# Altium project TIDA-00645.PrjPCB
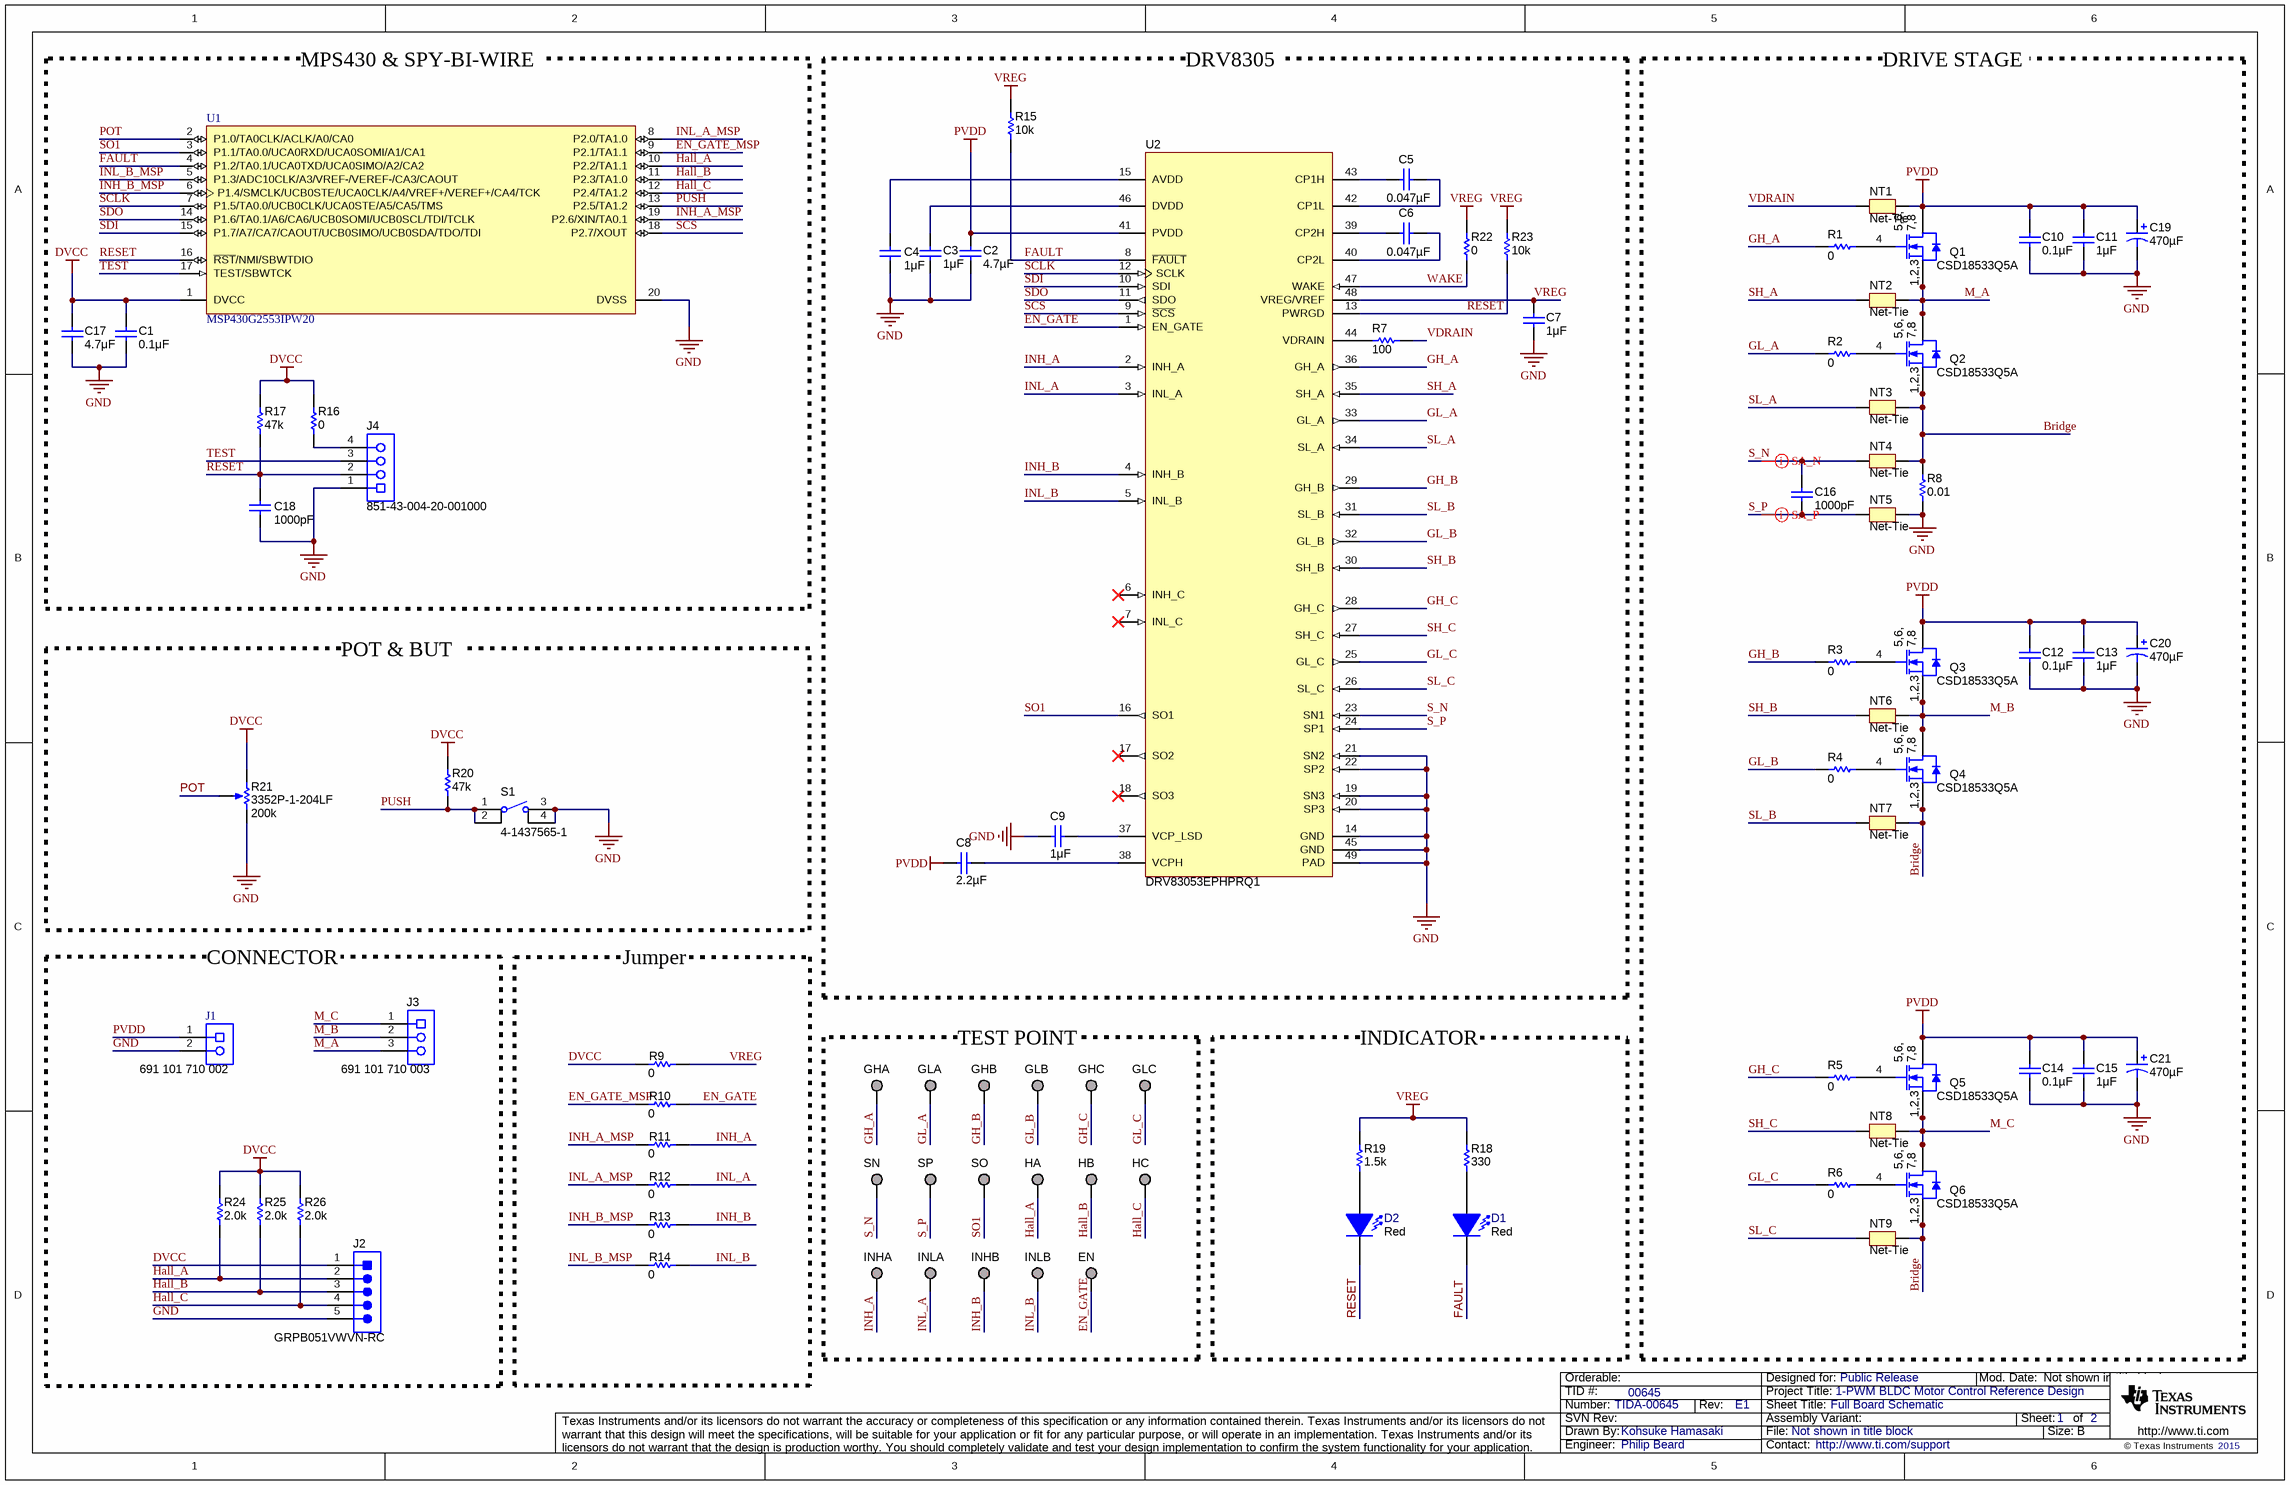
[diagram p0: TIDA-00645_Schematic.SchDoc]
TID: 00645; TechSupport: http://www.ti.com/support; SCH_Rev: E1; PRJ_Title: 1-PWM BLDC Motor Control Reference Design; PRJ_Number: TIDA-00645; PRJ_Engineer: Philip Beard; PRJ_Customer: Public Release; PCB_Rev: E1; PCB_Layout: Kohsuke Hamasaki; CopyrightYear: 2015
2 sheets, 98 parts. Net scope: global (net labels, ports and power ports of the same name join across sheets).
Board file: TIDA-00645_PCB layout.PcbDoc
Sheets:
  TIDA-00645_Schematic.SchDoc
  TIDA-00645_Hardware.SchDoc

## Sheet TIDA-00645_Schematic.SchDoc: Full Board Schematic
size 431 x 279 mm; Date: Not shown in title block; ApprovedBy: Not shown in title block; CheckedBy: Not shown in title block; Author: Not shown in title block; CompanyName: Not shown in title block; DrawnBy: Kohsuke Hamasaki; Engineer: Philip Beard; Organization: Not shown in title block; Address1: Not shown in title block; Address2: Not shown in title block; Address3: Not shown in title block; Address4: Not shown in title block; DocumentNumber: 1; Revision: Use project parameter SCH_Rev; SheetNumber: 1; SheetTotal: 2; PageSetup: Record=PageOptions¦CenterHorizontal=True¦CenterVertical=True¦PrintScale=1.00¦XCorrection=1.00¦YCorrection=1.00¦PrintKind=0¦BorderSize=5000000¦LeftOffset=0¦BottomOffset=0¦Orientation=2¦PaperLength=1000¦PaperWidth=1000¦Scale=100¦PaperSource=15¦PrintQuality=600¦MediaType=1¦DitherType=10¦PaperKind=Letter¦PrintScaleMode=1

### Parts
C1  ValueDisplayed: 0.1μF  [0603L]  (hidden comment: C0603C104K8RACTU)
C2  ValueDisplayed: 4.7µF  [0805L]  (hidden comment: C2012X5R1H475K125AB)
C3  ValueDisplayed: 1μF  [0603L]  (hidden comment: GRM185R61A105KE36D)
C4  ValueDisplayed: 1μF  [0603L]  (hidden comment: GRM185R61A105KE36D)
C5  ValueDisplayed: 0.047µF  [0603L]  (hidden comment: GRM188R71H473KA61D)
C6  ValueDisplayed: 0.047µF  [0603L]  (hidden comment: GRM188R71H473KA61D)
C7  ValueDisplayed: 1μF  [0603L]  (hidden comment: GRM185R61A105KE36D)
C8  ValueDisplayed: 2.2µF  [0805L]  (hidden comment: C2012X5R1H225K125AB)
C9  ValueDisplayed: 1μF  [0603L]  (hidden comment: GRM185R61A105KE36D)
C10  ValueDisplayed: 0.1µF  [0603L]  (hidden comment: GCM188R71H104KA57D)
C11  ValueDisplayed: 1μF  [0805L]  (hidden comment: GRM21BR71H105KA12L)
C12  ValueDisplayed: 0.1µF  [0603L]  (hidden comment: GCM188R71H104KA57D)
C13  ValueDisplayed: 1μF  [0805L]  (hidden comment: GRM21BR71H105KA12L)
C14  ValueDisplayed: 0.1µF  [0603L]  (hidden comment: GCM188R71H104KA57D)
C15  ValueDisplayed: 1μF  [0805L]  (hidden comment: GRM21BR71H105KA12L)
C16  ValueDisplayed: 1000pF  [0603L]  (hidden comment: GRM188R71C102KA01D)
C17  ValueDisplayed: 4.7μF  [0805L]  (hidden comment: C2012X7R1A475M)
C18  ValueDisplayed: 1000pF  [0603L]  (hidden comment: GRM188R71C102KA01D)
C19  ValueDisplayed: 470µF  [ZLH_1250x2500]  (hidden comment: 63ZLH470M12.5X25)
C20  ValueDisplayed: 470µF  [ZLH_1250x2500]  (hidden comment: 63ZLH470M12.5X25)
C21  ValueDisplayed: 470µF  [ZLH_1250x2500]  (hidden comment: 63ZLH470M12.5X25)
D1  value Red  [LED_LTST-C170]  (hidden comment: nFAULT)
D2  value Red  [LED_LTST-C170]  (hidden comment: PWRGD)
EN  TESTPOINT  [TP_25MIL-SMT]  (value not drawn)  (no BOM)
GHA  TESTPOINT  [TP_25MIL-SMT]  (value not drawn)  (no BOM)
GHB  TESTPOINT  [TP_25MIL-SMT]  (value not drawn)  (no BOM)
GHC  TESTPOINT  [TP_25MIL-SMT]  (value not drawn)  (no BOM)
GLA  TESTPOINT  [TP_25MIL-SMT]  (value not drawn)  (no BOM)
GLB  TESTPOINT  [TP_25MIL-SMT]  (value not drawn)  (no BOM)
GLC  TESTPOINT  [TP_25MIL-SMT]  (value not drawn)  (no BOM)
HA  TESTPOINT  [TP_25MIL-SMT]  (value not drawn)  (no BOM)
HB  TESTPOINT  [TP_25MIL-SMT]  (value not drawn)  (no BOM)
HC  TESTPOINT  [TP_25MIL-SMT]  (value not drawn)  (no BOM)
INHA  TESTPOINT  [TP_25MIL-SMT]  (value not drawn)  (no BOM)
INHB  TESTPOINT  [TP_25MIL-SMT]  (value not drawn)  (no BOM)
INLA  TESTPOINT  [TP_25MIL-SMT]  (value not drawn)  (no BOM)
INLB  TESTPOINT  [TP_25MIL-SMT]  (value not drawn)  (no BOM)
J1  691 101 710 002  [Wurth_691101710002]
J2  GRPB051VWVN-RC  [Sullins_GRPB051VWVN-RC]
J3  691 101 710 003  [Wurth_691101710003]
J4  851-43-004-20-001000  [CONN_851-43-004-20-001000]
NT1  Net-Tie  [Net-Tie_10mil]  (net tie, no BOM)
NT2  Net-Tie  [Net-Tie_10mil]  (net tie, no BOM)
NT3  Net-Tie  [Net-Tie_10mil]  (net tie, no BOM)
NT4  Net-Tie  [Net-Tie_10mil]  (net tie, no BOM)
NT5  Net-Tie  [Net-Tie_10mil]  (net tie, no BOM)
NT6  Net-Tie  [Net-Tie_10mil]  (net tie, no BOM)
NT7  Net-Tie  [Net-Tie_10mil]  (net tie, no BOM)
NT8  Net-Tie  [Net-Tie_10mil]  (net tie, no BOM)
NT9  Net-Tie  [Net-Tie_10mil]  (net tie, no BOM)
Q1  CSD18533Q5A  [TRANS_NexFET_Q5B]
Q2  CSD18533Q5A  [TRANS_NexFET_Q5B]
Q3  CSD18533Q5A  [TRANS_NexFET_Q5B]
Q4  CSD18533Q5A  [TRANS_NexFET_Q5B]
Q5  CSD18533Q5A  [TRANS_NexFET_Q5B]
Q6  CSD18533Q5A  [TRANS_NexFET_Q5B]
R1  ValueDisplayed: 0  [0402L]  (hidden comment: RC0402JR-070RL)
R2  ValueDisplayed: 0  [0402L]  (hidden comment: RC0402JR-070RL)
R3  ValueDisplayed: 0  [0402L]  (hidden comment: RC0402JR-070RL)
R4  ValueDisplayed: 0  [0402L]  (hidden comment: RC0402JR-070RL)
R5  ValueDisplayed: 0  [0402L]  (hidden comment: RC0402JR-070RL)
R6  ValueDisplayed: 0  [0402L]  (hidden comment: RC0402JR-070RL)
R7  ValueDisplayed: 100  [0402L]  (hidden comment: CRCW0402100RJNED)
R8  ValueDisplayed: 0.01  [2512]  (hidden comment: PMR100HZPFU10L0)
R9  ValueDisplayed: 0  [0402L]  (hidden comment: RC0402JR-070RL)
R10  ValueDisplayed: 0  [0402L]  (hidden comment: RC0402JR-070RL)
R11  ValueDisplayed: 0  [0402L]  (hidden comment: RC0402JR-070RL)
R12  ValueDisplayed: 0  [0402L]  (hidden comment: RC0402JR-070RL)
R13  ValueDisplayed: 0  [0402L]  (hidden comment: RC0402JR-070RL)
R14  ValueDisplayed: 0  [0402L]  (hidden comment: RC0402JR-070RL)
R15  ValueDisplayed: 10k  [0402L]  (hidden comment: CRCW040210K0JNED)
R16  value 0  [0603L]  (hidden comment: CRCW06030000Z0EA)
R17  value 47k  [0603L]  (hidden comment: CRCW060347K0JNEA)
R18  ValueDisplayed: 330  [0603L]  (hidden comment: RC0603FR-07330RL)
R19  ValueDisplayed: 1.5k  [0603L]  (hidden comment: CRCW06031K50JNEA)
R20  value 47k  [0603L]  (hidden comment: CRCW060347K0JNEA)
R21  3352P-1-204LF  value 200k  [Bourns_3352P]
R22  ValueDisplayed: 0  [0402L]  (hidden comment: RC0402JR-070RL)
R23  ValueDisplayed: 10k  [0402L]  (hidden comment: CRCW040210K0JNED)
R24  ValueDisplayed: 2.0k  [0402L]  (hidden comment: CRCW04022K00JNED)
R25  ValueDisplayed: 2.0k  [0402L]  (hidden comment: CRCW04022K00JNED)
R26  ValueDisplayed: 2.0k  [0402L]  (hidden comment: CRCW04022K00JNED)
S1  4-1437565-1  [SW_FSM4JSMA]
SN  TESTPOINT  [TP_25MIL-SMT]  (value not drawn)  (no BOM)
SO  TESTPOINT  [TP_25MIL-SMT]  (value not drawn)  (no BOM)
SP  TESTPOINT  [TP_25MIL-SMT]  (value not drawn)  (no BOM)
U1  MSP430G2553IPW20  [PW0020A_L]
U2  DRV83053EPHPRQ1  [PHP0048G_N]

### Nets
DVCC: C1.1 C17.1 J2.1 R9.1 R16.2 R17.2 R20.2 R21.1(CCW) R24.2 R25.2 R26.2 U1.1(DVCC)
GND: C1.2 C2.2 C3.2 C4.2 C7.2 C9.1 C10.2 C11.2 C12.2 C13.2 C14.2 C15.2 C17.2 C18.2 C19.2(-) C20.2(-) C21.2(-) J1.2 J2.5 J4.1 NT5.2 R8.1 R21.3(CW) S1.3 S1.4 U1.20(DVSS) U2.14(GND) U2.19(SN3) U2.20(SP3) U2.21(SN2) U2.22(SP2) U2.45(GND) U2.49(PAD)
PVDD: C2.1 C8.1 C10.1 C11.1 C12.1 C13.1 C14.1 C15.1 C19.1(+) C20.1(+) C21.1(+) J1.1 NT1.2 Q1.5(D) Q1.6(D) Q1.7(D) Q1.8(D) Q3.5(D) Q3.6(D) Q3.7(D) Q3.8(D) Q5.5(D) Q5.6(D) Q5.7(D) Q5.8(D) U2.41(PVDD)
VREG: C7.1 R9.2 R15.2 R18.2 R19.2 R22.2 R23.2 U2.48(VREG/VREF)
Bridge: NT3.2 NT4.2 NT7.2 NT9.2 Q2.1(S) Q2.2(S) Q2.3(S) Q4.1(S) Q4.2(S) Q4.3(S) Q6.1(S) Q6.2(S) Q6.3(S) R8.2
EN_GATE: EN.1 R10.2 U2.1(EN_GATE)
EN_GATE_MSP: R10.1 U1.9(P2.1/TA1.1)
FAULT: D1.2(K) R15.1 U1.4(P1.2/TA0.1/UCA0TXD/UCA0SIMO/A2/CA2) U2.8(~{FAULT})
GH_A: GHA.1 R1.1 U2.36(GH_A)
GH_B: GHB.1 R3.1 U2.29(GH_B)
GH_C: GHC.1 R5.1 U2.28(GH_C)
GL_A: GLA.1 R2.1 U2.33(GL_A)
GL_B: GLB.1 R4.1 U2.32(GL_B)
GL_C: GLC.1 R6.1 U2.25(GL_C)
Hall_A: HA.1 J2.2 R24.1 U1.10(P2.2/TA1.1)
Hall_B: HB.1 J2.3 R25.1 U1.11(P2.3/TA1.0)
Hall_C: HC.1 J2.4 R26.1 U1.12(P2.4/TA1.2)
INH_A: INHA.1 R11.2 U2.2(INH_A)
INH_A_MSP: R11.1 U1.19(P2.6/XIN/TA0.1)
INH_B: INHB.1 R13.2 U2.4(INH_B)
INH_B_MSP: R13.1 U1.6(P1.4/SMCLK/UCB0STE/UCA0CLK/A4/VREF+/VEREF+/CA4/TCK)
INL_A: INLA.1 R12.2 U2.3(INL_A)
INL_A_MSP: R12.1 U1.8(P2.0/TA1.0)
INL_B: INLB.1 R14.2 U2.5(INL_B)
INL_B_MSP: R14.1 U1.5(P1.3/ADC10CLK/A3/VREF-/VEREF-/CA3/CAOUT)
M_A: J3.3 NT2.2 Q1.1(S) Q1.2(S) Q1.3(S) Q2.5(D) Q2.6(D) Q2.7(D) Q2.8(D)
M_B: J3.2 NT6.2 Q3.1(S) Q3.2(S) Q3.3(S) Q4.5(D) Q4.6(D) Q4.7(D) Q4.8(D)
M_C: J3.1 NT8.2 Q5.1(S) Q5.2(S) Q5.3(S) Q6.5(D) Q6.6(D) Q6.7(D) Q6.8(D)
POT: R21.2(WIPER) U1.2(P1.0/TA0CLK/ACLK/A0/CA0)
PUSH: R20.1 S1.1 S1.2 U1.13(P2.5/TA1.2)
RESET: C18.1 D2.2(K) J4.2 R17.1 R23.1 U1.16(~{RST}/NMI/SBWTDIO) U2.13(PWRGD)
S_N: C16.1 NT4.1 SN.1 U2.23(SN1)
S_P: C16.2 NT5.1 SP.1 U2.24(SP1)
SCLK: U1.7(P1.5/TA0.0/UCB0CLK/UCA0STE/A5/CA5/TMS) U2.12(SCLK)
SCS: U1.18(P2.7/XOUT) U2.9(~{SCS})
SDI: U1.15(P1.7/A7/CA7/CAOUT/UCB0SIMO/UCB0SDA/TDO/TDI) U2.10(SDI)
SDO: U1.14(P1.6/TA0.1/A6/CA6/UCB0SOMI/UCB0SCL/TDI/TCLK) U2.11(SDO)
SH_A: NT2.1 U2.35(SH_A)
SH_B: NT6.1 U2.30(SH_B)
SH_C: NT8.1 U2.27(SH_C)
SL_A: NT3.1 U2.34(SL_A)
SL_B: NT7.1 U2.31(SL_B)
SL_C: NT9.1 U2.26(SL_C)
SO1: SO.1 U1.3(P1.1/TA0.0/UCA0RXD/UCA0SOMI/A1/CA1) U2.16(SO1)
TEST: J4.3 U1.17(TEST/SBWTCK)
VDRAIN: NT1.1 R7.2
WAKE: R22.1 U2.47(WAKE)
NetC3_1: C3.1 U2.46(DVDD)
NetC4_1: C4.1 U2.15(AVDD)
NetC5_1: C5.1 U2.42(CP1L)
NetC5_2: C5.2 U2.43(CP1H)
NetC6_1: C6.1 U2.40(CP2L)
NetC6_2: C6.2 U2.39(CP2H)
NetC8_2: C8.2 U2.38(VCPH)
NetC9_2: C9.2 U2.37(VCP_LSD)
NetD1_1: D1.1(A) R18.1
NetD2_1: D2.1(A) R19.1
NetJ4_4: J4.4 R16.1
NetQ1_4: Q1.4(G) R1.2
NetQ2_4: Q2.4(G) R2.2
NetQ3_4: Q3.4(G) R3.2
NetQ4_4: Q4.4(G) R4.2
NetQ5_4: Q5.4(G) R5.2
NetQ6_4: Q6.4(G) R6.2
NetR7_1: R7.1 U2.44(VDRAIN)

Not connected (* = marked no-connect by the designer): U2 6(INH_C)* 7(INL_C)* 17(SO2)* 18(SO3)*

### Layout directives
differential pair: S_N, S_P

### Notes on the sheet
- MPS430 & SPY-BI-WIRE
- DRV8305
- DRIVE STAGE
- POT & BUT
- CONNECTOR
- Jumper
- TEST POINT
- INDICATOR

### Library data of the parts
C1 = C0603C104K8RACTU: CAP, CERM, 0.1uF, 10V, +/-10%, X7R, 0603; Manufacturer: Kemet; Polarized: N; CompType: Capacitor; U/M: EA; Cap_F: 0.0000001; Tolerance_%: 10; Value1: Unknown; TaMin_C: -55; TaMax_C: 125; Cap_Case: 0603
C2 = C2012X5R1H475K125AB: CAP, CERM, 4.7 µF, 50 V, +/- 10%, X5R, 0805; Manufacturer: TDK; Polarized: N; CompType: Capacitor; Value: 4.7uF; U/M: EA; Cap_F: 0.0000047; Tolerance_%: 10; Value1: Unknown; VDC_V: 50; Value2: 50V; TaMin_C: -55; TaMax_C: 85; Cap_Case: 0805
C3 C4 C7 C9 = GRM185R61A105KE36D: CAP, CERM, 1 ｵF, 10 V, +/- 10%, X5R, 0603; Manufacturer: MuRata; Polarized: N; CompType: Capacitor; Value: 1uF; U/M: EA; Cap_F: 0.000001; Tolerance_%: 10; Value1: Unknown; Value2: 10V; TaMin_C: -55; TaMax_C: 85; Cap_Case: 0603
C5 C6 = GRM188R71H473KA61D: CAP, CERM, 0.047 µF, 50 V, +/- 10%, X7R, 0603; Manufacturer: MuRata; Polarized: N; CompType: Capacitor; Value: 0.047uF; U/M: EA; Cap_F: 0.000000047; Tolerance_%: 10; Value1: Unknown; VDC_V: 50; Value2: 50V; TaMin_C: -55; TaMax_C: 125; Cap_Case: 0603
C8 = C2012X5R1H225K125AB: CAP, CERM, 2.2 µF, 50 V, +/- 10%, X5R, 0805; Manufacturer: TDK; Polarized: N; CompType: Capacitor; Value: 2.2uF; U/M: EA; Cap_F: 0.0000022; Tolerance_%: 10; Value1: Unknown; VDC_V: 50; Value2: 50V; TaMin_C: -55; TaMax_C: 85; Cap_Case: 0805
C10 C12 C14 = GCM188R71H104KA57D: CAP, CERM, 0.1 µF, 50 V, +/- 10%, X7R, 0603; Manufacturer: MuRata; Polarized: N; CompType: Capacitor; Value: 0.1uF; U/M: EA; Cap_F: 0.0000001; Tolerance_%: 10; ESR_ohm: 0.02; Value1: 0.02 ohm; VDC_V: 50; Value2: 50V; IRMS_A: 1.84; TaMin_C: -55; TaMax_C: 125; Cap_Case: 0603
C11 C13 C15 = GRM21BR71H105KA12L: CAP, CERM, 1uF, 50V, +/-10%, X7R, 0805; Manufacturer: MuRata; Polarized: N; CompType: Capacitor; U/M: EA; Cap_F: 0.000001; Tolerance_%: 10; Value1: Unknown; VDC_V: 50; TaMin_C: -55; TaMax_C: 125; Cap_Case: 0805
C16 C18 = GRM188R71C102KA01D: CAP, CERM, 1000pF, 16V, +/-10%, X7R, 0603; Manufacturer: MuRata; Polarized: N; CompType: Capacitor; U/M: EA; Cap_F: 0.000000001; Tolerance_%: 10; Value1: Unknown; VDC_V: 16; TaMin_C: -55; TaMax_C: 125; Cap_Case: 0603
C17 = C2012X7R1A475M: CAP, CERM, 4.7uF, 10V, +/-20%, X7R, 0805; Manufacturer: TDK; Polarized: N; CompType: Capacitor; U/M: EA; Cap_F: 0.0000047; Tolerance_%: 20; Value1: Unknown; VDC_V: 10; TaMin_C: -55; TaMax_C: 125; Cap_Case: 0805
C19-C21 = 63ZLH470M12.5X25: CAP, AL, 470 µF, 63 V, +/- 20%, 0.043 ohm, TH; Manufacturer: Rubycon; Polarized: Y; CompType: Capacitor; Value: 470uF; U/M: EA; Cap_F: 0.00047; Tolerance_%: 20; VDC_V: 63; Value2: 63V; ESR_ohm: 0.043; IRMS_A: 1.99; TaMin_C: -40; TaMax_C: 105
D1 D2 = LTST-C170KRKT: LED, Red, SMD; Manufacturer: Lite-On; DK Part Number: 160-1415-1-ND; Type: AlInGaP; Vf_V: 2; Value2: 2V; Value1: W; U/M: EA
EN GHA GHB GHC GLA GLB GLC HA HB HC INHA INHB INLA INLB SN SO SP = TESTPOINT: TEST POINT.  No entry in BOM.
J1 = 691 101 710 002: Terminal Block, 5 mm, 2x1, Tin, TH; Manufacturer: Wurth Elektronik eiSos; SymbolCreator: a0412235; U/M: EA
J2 = GRPB051VWVN-RC: Header, 50mil, 5x1, Gold, TH; Manufacturer: Sullins Connector Solutions; SymbolCreator: a0412235; U/M: EA
J3 = 691 101 710 003: Terminal Block, 5 mm, 3x1, Tin, TH; Manufacturer: Wurth Elektronik eiSos; SymbolCreator: a0412235; U/M: EA
J4 = 851-43-004-20-001000: SOCKET .050" GRID SIP 4 POS R/A, TH; Manufacturer: Mill-Max; SymbolCreator: a0411947; CompType: Header; U/M: EA
NT1-NT9 = Net-Tie: Single point connection between nets.; SymbolCreator: codlsc
Q1-Q6 = CSD18540Q5B: MOSFET, N-CH, 60 V, 28 A, SON 5x6mm; Manufacturer: Texas Instruments; Alternate Manufacturer: None; U/M: EA; ChType: N; Value: 60V; VdsMax_V: 60; Value1: 0.0033 ohm; Rdson45_ohm: 0.0033; Value2: 41 nC; QgTyp_nC: 41; Vgs_V: 20; IdsMax_A: 28
R1-R6 R9-R14 R22 = RC0402JR-070RL: RES, 0, 5%, 0.063 W, 0402; Manufacturer: Yageo America; CompType: Resistor; Value: 0; Value_Code: 0000; Tolerance_%: 5; Power_W: 0.063; Value2: 0.063W; VDC_V: 50; TempCo: 200 ppm/C; EIA_Code: E24; U/M: EA
R7 = CRCW0402100RJNED: RES, 100, 5%, 0.063 W, 0402; Manufacturer: Vishay-Dale; CompType: Resistor; Value: 100; Value_Code: 100R; Tolerance_%: 5; Power_W: 0.063; Value2: 0.063W; VDC_V: 50; TempCo: 200 ppm/C; EIA_Code: E24; U/M: EA
R8 = PMR100HZPFU10L0: RES, 0.01, 1%, 2 W, 2512; Manufacturer: Rohm; CompType: Resistor; Value: 0.01; Value_Code: R010; Tolerance_%: 1; Power_W: 2; Value2: 2W; TempCo: 100 ppm/C; EIA_Code: E96; U/M: EA
R15 R23 = CRCW040210K0JNED: RES, 10 k, 5%, 0.063 W, 0402; Manufacturer: Vishay-Dale; CompType: Resistor; Value: 10k; Res_ohm: 10000; Value_Code: 10k0; Tolerance_%: 5; Power_W: 0.063; Value2: 0.063W; VDC_V: 50; TempCo: 200 ppm/C; EIA_Code: E24; U/M: EA
R16 = CRCW06030000Z0EA: RES, 0 ohm, 5%, 0.1W, 0603; Manufacturer: Vishay-Dale; CompType: Resistor; Value_Code: 0000; Tolerance_%: 5; Power_W: 0.1; VDC_V: 75; TempCo: 200 ppm/C; EIA_Code: E24; U/M: EA
R17 = CRCW060347K0JNEA: RES, 47k ohm, 5%, 0.1W, 0603; Manufacturer: Vishay-Dale; CompType: Resistor; Res_ohm: 47000; Value_Code: 47k0; Tolerance_%: 5; Power_W: 0.1; VDC_V: 75; TempCo: 200 ppm/C; EIA_Code: E24; U/M: EA
R18 = RC0603FR-07330RL: RES, 330, 1%, 0.1 W, 0603; Manufacturer: Yageo America; CompType: Resistor; Value: 330; Value_Code: 330R; Tolerance_%: 1; Power_W: 0.1; Value2: 0.1W; VDC_V: 150; TempCo: 200 ppm/C; U/M: EA
R19 = CRCW06031K50JNEA: RES, 1.5 k, 5%, 0.1 W, 0603; Manufacturer: Vishay-Dale; CompType: Resistor; Value: 1.5k; Res_ohm: 1500; Value_Code: 1k50; Tolerance_%: 5; Power_W: 0.1; Value2: 0.1W; VDC_V: 75; TempCo: 200 ppm/C; EIA_Code: E24; U/M: EA
R20 = CRCW060347K0JNEA: RES 47K OHM 1/10W 5% 0603 SMD; Manufacturer: Vishay-Dale; CompType: Resistor; Res_ohm: 47000; Value_Code: 47k0; Tolerance_%: 5; Power_W: 0.1; Value2: 0.1W; VDC_V: 75; TempCo: 200 ppm/C; EIA_Code: E24; U/M: EA
R21 = 3352P-1-204LF: Trimmer, 200 K, 0.5 W, TH; Manufacturer: Bourns; Sim Note: Enter the Resistance value and the set point into parameter fields.; SymbolCreator: a0412235
R24-R26 = CRCW04022K00JNED: RES, 2.0 k, 5%, 0.063 W, 0402; Manufacturer: Vishay-Dale; CompType: Resistor; Value: 2.0k; Res_ohm: 2000; Value_Code: 2k00; Tolerance_%: 5; Power_W: 0.063; Value2: 0.063W; VDC_V: 50; TempCo: 200 ppm/C; EIA_Code: E24; U/M: EA
S1 = 4-1437565-1: SWITCH TACTILE SPST-NO 0.05A 12V; Manufacturer: TE Connectivity; SymbolCreator: a0412235; VDC_V: 12; SwitchFunction: Off-Mom; PositionCount: 1; CurrentRating_mA: 50
U1 = MSP430G2553IPW20: 16 MHz Mixed Signal Microcontroller with 16 KB Flash, 512 B SRAM and 24 GPIOs, -40 to 85 degC, 20-pin SOP (PW), Green (RoHS & no Sb/Br); Alternate Manufacturer: Texas Instruments; Alternate PartNumber: Equivalent; ADC: 10-bit SAR; ADC Channels: 8; Brown Out Reset: Yes; Flash(KB): 16; GPIO: 24; Pin/Package: 0DIESALE, 0WAFERSALE, 20PDIP, 20TSSOP, 28TSSOP, 32QFN; SRAM(B): 512; SubFamily: Value Line; Timers - 16-bit: 2; USCI_A (UART/LIN/IrDA/SPI): 1
U2 = DRV83053EPHPRQ1: Three Phase Automotive Gate Driver with Three Integrated Current Shunt Amplifiers and Voltage Regulator, PHP0048G; Alternate PartNumber: DRV83053EPHPQ1; Manufacturer: Texas Instruments; SymbolCreator: Altium; CompType: IC; U/M: EA

## Sheet TIDA-00645_Hardware.SchDoc
size 431 x 279 mm; Date: Not shown in title block; ApprovedBy: Not shown in title block; CheckedBy: Not shown in title block; Author: Not shown in title block; CompanyName: Not shown in title block; Engineer: Not shown in title block; Organization: Not shown in title block; Address1: Not shown in title block; Address2: Not shown in title block; Address3: Not shown in title block; Address4: Not shown in title block; DocumentNumber: 1; Revision: Use project parameter SCH_Rev; SheetNumber: 2; SheetTotal: 2; PageSetup: Record=PageOptions¦CenterHorizontal=True¦CenterVertical=True¦PrintScale=1.00¦XCorrection=1.00¦YCorrection=1.00¦PrintKind=0¦BorderSize=5000000¦LeftOffset=0¦BottomOffset=0¦Orientation=2¦PaperLength=1000¦PaperWidth=1000¦Scale=100¦PaperSource=15¦PrintQuality=600¦MediaType=1¦DitherType=10¦PaperKind=Letter¦PrintScaleMode=1
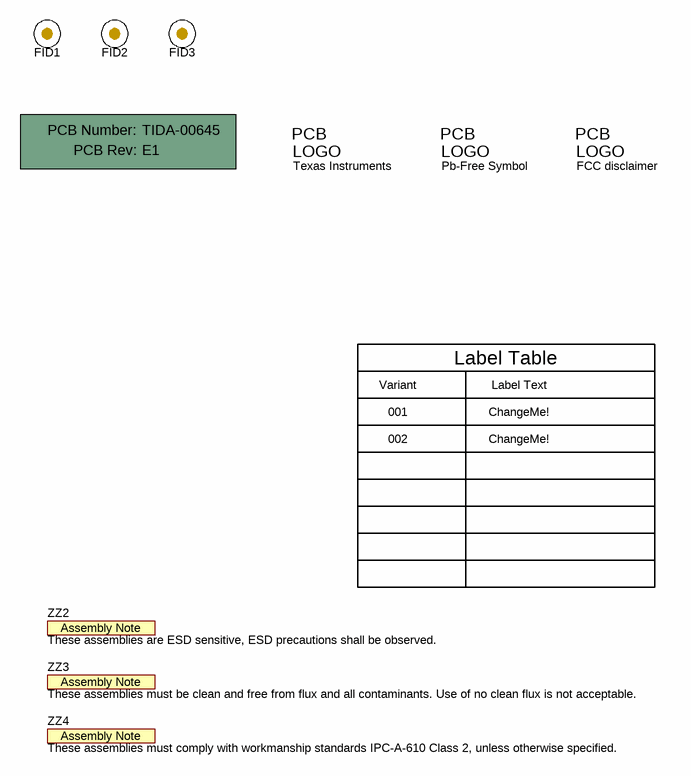
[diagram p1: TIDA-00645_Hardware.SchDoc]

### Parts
!PCB  Printed Circuit Board  (value not drawn)  (mechanical)
FID1  Fiducial  [Fiducial10-20]  (value not drawn)
FID2  Fiducial  [Fiducial10-20]  (value not drawn)
FID3  Fiducial  [Fiducial10-20]  (value not drawn)
Logo1  Texas Instruments  [TI_Stacked_Overlay_Small]  (no BOM)
Logo2  Pb-Free Symbol  [Pb-Free_Overlay_Small]  (no BOM)
Logo3  FCC disclaimer  [FCC_disclaimer_stacked]  (no BOM)
ZZ2  These assemblies are ESD sensitive, ESD precautions shall be observed.  [AssemblyNote]  (no BOM)
ZZ3  These assemblies must be clean and free from flux and all contaminants. Use of no clean flux is not acceptable.  [AssemblyNote]  (no BOM)
ZZ4  These assemblies must comply with workmanship standards IPC-A-610 Class 2, unless otherwise specified.  [AssemblyNote]  (no BOM)

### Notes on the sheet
- Variant
- Label Table
- Label Text
- 001
- 002
- ChangeMe!

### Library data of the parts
!PCB = PCB: Manufacturer: Any; PartNumber: TIDA-00645; SymbolCreator: a0412235
FID1-FID3 = Fiducial: Fiducial mark.  There is nothing to buy or mount.; SymbolCreator: codlsc
Logo1 = TI_Logo: Texas Instrument Corporate Signature; SymbolCreator: codlsc
Logo2 = Pb-Free: SymbolCreator: a0412235
Logo3 = FCC_disclaimer: SymbolCreator: codlsc
ZZ2-ZZ4 = AssemblyNote: SymbolCreator: codlsc

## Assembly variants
001: not fitted FID1 FID2 FID3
